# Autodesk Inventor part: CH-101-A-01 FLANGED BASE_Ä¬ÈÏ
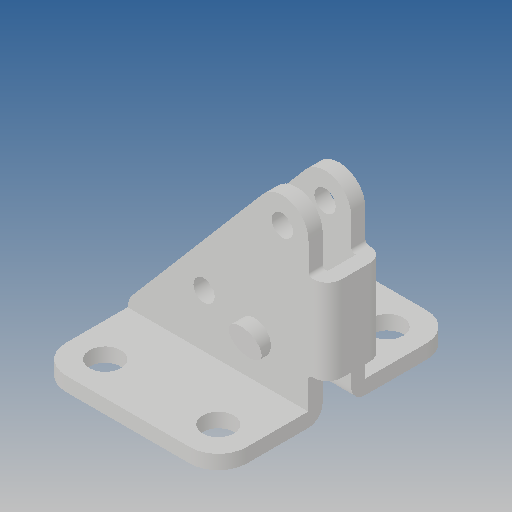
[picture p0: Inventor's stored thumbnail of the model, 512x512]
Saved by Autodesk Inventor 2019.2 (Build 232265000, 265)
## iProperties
Created: 2010-06
Part Number: CH-101-A-01 FLANGED BASE_Ä¬ÈÏ
Material: Ogólny
Document SubType Name: Modeling
Designer: CADENGINEERING4
Density: 1 g/cm^3
Appearance: Domyślna
Author: CADENGINEERING4
Revision Number: ÈÎºÎ
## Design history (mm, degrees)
feature "NONE"
node "Bryła1"
